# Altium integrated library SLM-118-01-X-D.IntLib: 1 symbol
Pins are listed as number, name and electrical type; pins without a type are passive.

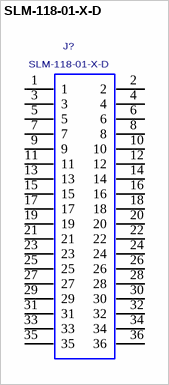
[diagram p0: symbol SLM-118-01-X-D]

## SLM-118-01-X-D
designator J?
LOW PROFILE, DOUBLE ROW, 0.050"SOCKET STRIP ASSEMBLY.; MANUFACTURER: SAMTEC
footprint SLM-118-01-X-D
pins: 1, 2, 3, 4, 5, 6, 7, 8, 9, 10, 11, 12, 13, 14, 15, 16, 17, 18, 19, 20, 21, 22, 23, 24, 25, 26, 27, 28, 29, 30, 31, 32, 33, 34, 35, 36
